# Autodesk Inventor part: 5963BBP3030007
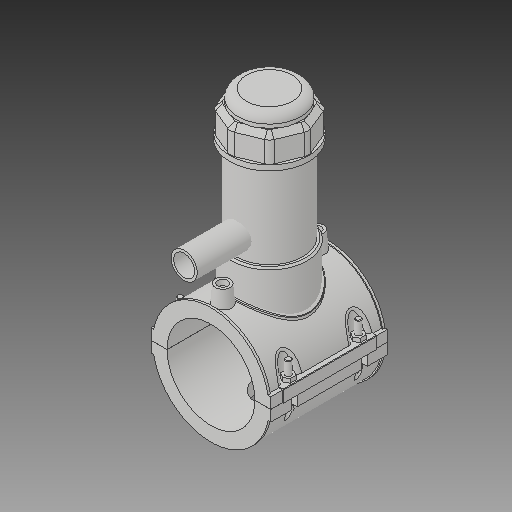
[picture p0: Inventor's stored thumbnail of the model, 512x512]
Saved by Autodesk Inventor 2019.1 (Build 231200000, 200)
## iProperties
Created: 2017-07
Part Number: 5963BBP3030007
Material: Generic
Description: PLASSON TAPPING SADDLE 3''IPS x 3/4''IPS
Document SubType Name: Modeling
Designer: KIM
Density: 1 g/cm^3
Appearance: Default
Author: KIM
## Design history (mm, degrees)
derived "5963BBP_5963BUP.ipt"
feature "Solid1::5963BBP_5963BUP.ipt"
feature "Solid2::5963BBP_5963BUP.ipt"
feature "Solid3::5963BBP_5963BUP.ipt"
tag "TaggingFeature1"
body "Solid1"
body "Solid2"
body "Solid3"
other parameters: "d_" = 88.7, "B_" = 120.904, "L_" = 118.11, "d_t" = 6, "H_2" = 177.038, "H_1" = 65.024, "d_1" = 26.6, "H_" = 86.106, "d1" = 115.31, "d148" = 1.3305, "d160" = 1.3305, "d169" = 3.2805, "d192" = 6.9984, "d0" = 88.7, "d2" = 120.904, "d3" = 22.175, "d4" = 118.11, "d5" = 0, "d6" = 0.1, "d8" = 0, "d19" = 6, "d20" = 6, "d21" = 70.866, "d23" = 0, "d24" = 35.433, "d26" = 0, "d27" = 3, "d28" = 3, "d29" = 3, "d30" = 29.56667, "d31" = 6, "d32" = 0, "d33" = 0, "d34" = 0.6, "d40" = 59.9612, "d41" = 79.83, "d43" = 0, "d45" = 0, "d47" = 128.521, "d70" = 15, "d72" = 0, "d73" = 6, "d75" = 5, "d76" = 0, "d77" = 4.435, "d78" = 74.35, "d79" = 15, "d80" = 47.244, "d82" = 5 deg, "d84" = 4, "d85" = 14, "d86" = 0, "d87" = 3, "d88" = 0, "d89" = 1, "d90" = 1, "d91" = 94.488, "d92" = 0, "d93" = 0.5, "d94" = 46.68421, "d96" = 117.6162, "d97" = 2.3622, "d98" = 0, "d102" = 0.887, "d120" = 140 deg, "d121" = 24.228, "d122" = 20 deg, "d123" = 230.62, "d124" = 69.186, "d126" = 0, "d143" = 91.361, "d145" = 20.46923, "d149" = 1.3305, "d150" = 22.51615, "d153" = 118.11, "d154" = 0, "d156" = 57.655, "d157" = 160 deg, "d159" = 5.322, "d161" = 1.3305, "d162" = 70.866, "d163" = 0, "d164" = 44.35, "d167" = 8.87, "d168" = 56.24878, "d170" = 3.2805, "d172" = 0, "d173" = 1, "d175" = 44.35, "d176" = 20 deg, "d177" = 6.209, "d178" = 26.61, "d180" = 0, "d183" = 10.644, "d184" = 4.9672, "d185" = 38.38575, "d186" = 38.38575, "d187" = 57.655, "d188" = 7.983, "d189" = 6.209, "d190" = 0, "d191" = 86.4825, "d193" = 6.9984, "d194" = 4.13385, "d195" = 90 deg, "d197" = 0, "d199" = 0, "d200" = 13.305, "d202" = 0, "d203" = 177.038, "d204" = 75.8385, "d205" = 55.881, "d206" = 67.8555, "d207" = 132.7785, "d208" = 138.08964, "d209" = 164.64534, "d210" = 68.6538, "d211" = 79.83, "d212" = 63.864, "d213" = 46.5516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
